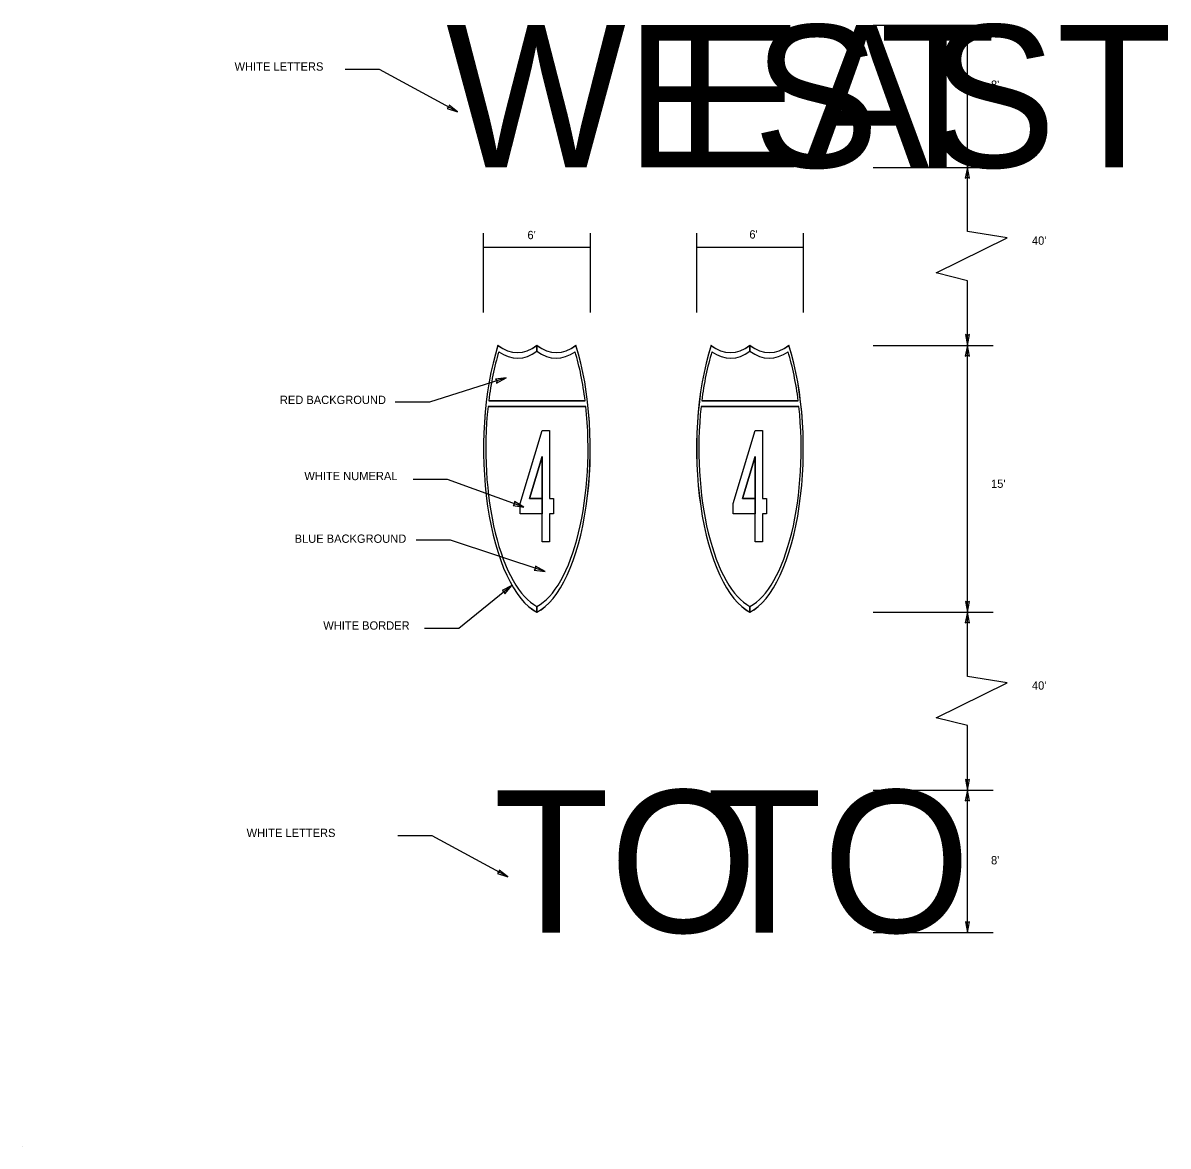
# Model space of a CAD drawing. Extents: x -274 to 353, y -329 to 85.
# Drawn here: x -273.7 to 112.5, y -328.7 to 50 of the extents above; entities that cross this region are included whole.
import ezdxf

# ---------------------------------------------------------------- set-up
doc = ezdxf.new("R2010")
doc.units = 0
for name, color, linetype in [('52', 7, 'Continuous'), ('AdhocPoint_dp', 7, 'Continuous'), ('DimLines_dp', 7, 'Continuous'), ('PavtMessage_Horizontal', 7, 'Continuous'), ('TextLabel', 7, 'Continuous')]:
    doc.layers.add(name, color=color, linetype=linetype)

msp = doc.modelspace()

# ---------------------------------------------------------------- linework, layer by layer
at = {"layer": '52'}
for p, q in [((44.85, 49.32), (44.15, 45.7)), ((45.52, 45.7), (44.85, 49.32)), ((44.15, 45.7), (44.85, 45.97)), ((44.85, 45.97), (45.52, 45.7)), ((-130.08, 21.6), (-130.64, 21.14)), ((-130.64, 21.14), (-127.13, 20)), ((-129.98, 22.34), (-130.08, 21.6)), ((-127.13, 20), (-129.98, 22.34)), ((44.85, 4.67), (44.17, 4.95)), ((44.17, 4.95), (44.85, 1.32)), ((44.85, 1.32), (45.55, 4.95)), ((45.55, 4.95), (44.85, 4.67)), ((44.85, 1.32), (44.15, -2.3)), ((45.52, -2.3), (44.85, 1.32)), ((44.15, -2.3), (44.85, -2.03)), ((44.85, -2.03), (45.52, -2.3)), ((44.85, -55.33), (44.17, -55.05)), ((44.17, -55.05), (44.85, -58.68)), ((44.85, -58.68), (45.55, -55.05)), ((45.55, -55.05), (44.85, -55.33)), ((44.85, -58.68), (44.15, -62.3)), ((45.52, -62.3), (44.85, -58.68)), ((44.15, -62.3), (44.85, -62.03)), ((44.85, -62.03), (45.52, -62.3)), ((-110.7, -69.68), (-114.37, -70.1)), ((-114.37, -70.1), (-113.9, -70.68)), ((-113.96, -71.41), (-110.7, -69.68)), ((-113.9, -70.68), (-113.96, -71.41)), ((-104.73, -113.23), (-107.9, -111.34)), ((-107.9, -111.34), (-107.88, -112.09)), ((-107.88, -112.09), (-108.36, -112.63)), ((-108.36, -112.63), (-104.73, -113.23)), ((-100.79, -133.89), (-101.26, -134.44)), ((-101.26, -134.44), (-97.61, -134.94)), ((-97.61, -134.94), (-100.83, -133.14)), ((-100.83, -133.14), (-100.79, -133.89)), ((-108.76, -139.62), (-112.01, -141.37)), ((-112.01, -141.37), (-111.35, -141.73)), ((-111.35, -141.73), (-111.14, -142.43)), ((-111.14, -142.43), (-108.76, -139.62)), ((44.85, -145.33), (44.17, -145.05)), ((44.17, -145.05), (44.85, -148.68)), ((44.85, -148.68), (45.55, -145.05)), ((45.55, -145.05), (44.85, -145.33)), ((44.85, -148.68), (44.15, -152.3)), ((45.52, -152.3), (44.85, -148.68)), ((44.15, -152.3), (44.85, -152.03)), ((44.85, -152.03), (45.52, -152.3)), ((44.85, -205.33), (44.17, -205.05)), ((44.17, -205.05), (44.85, -208.68)), ((44.85, -208.68), (45.55, -205.05)), ((45.55, -205.05), (44.85, -205.33)), ((44.85, -208.68), (44.15, -212.3)), ((44.15, -212.3), (44.85, -212.03)), ((45.52, -212.3), (44.85, -208.68)), ((44.85, -212.03), (45.52, -212.3)), ((-113.03, -235.61), (-113.12, -236.35)), ((-110.18, -237.95), (-113.03, -235.61)), ((-113.12, -236.35), (-113.69, -236.82)), ((-113.69, -236.82), (-110.18, -237.95)), ((44.85, -253.33), (44.17, -253.05)), ((44.17, -253.05), (44.85, -256.68)), ((44.85, -256.68), (45.55, -253.05)), ((45.55, -253.05), (44.85, -253.33))]:
    msp.add_line(p, q, dxfattribs=at)
at = {"layer": 'AdhocPoint_dp'}
msp.add_line((-273.71, -328.68), (-273.71, -328.68), dxfattribs=at)
at = {"layer": 'DimLines_dp'}
for p, q in [((13.04, 49.32), (48.19, 49.32)), ((44.85, 1.32), (44.85, 49.32)), ((-153.47, 34.31), (-165.05, 34.31)), ((-127.13, 20), (-153.47, 34.31)), ((13.04, 1.32), (48.19, 1.32)), ((44.85, -20.35), (44.85, 1.32)), ((-118.31, -47.57), (-118.31, -20.9)), ((-82.31, -47.57), (-82.31, -20.9)), ((-46.46, -47.57), (-46.46, -20.9)), ((-10.46, -47.57), (-10.46, -20.9)), ((34.33, -34.26), (58.21, -22.48)), ((58.21, -22.48), (44.85, -20.35)), ((-82.31, -25.74), (-118.31, -25.74)), ((-10.46, -25.74), (-46.46, -25.74)), ((44.85, -36.89), (34.33, -34.26)), ((44.85, -58.68), (44.85, -36.89)), ((13.04, -58.68), (53.52, -58.68)), ((44.85, -148.68), (44.85, -58.68)), ((-110.7, -69.68), (-136.57, -77.79)), ((-136.57, -77.79), (-148.15, -77.79)), ((-130.5, -103.91), (-142.07, -103.91)), ((-104.73, -113.23), (-130.5, -103.91)), ((-129.5, -124.41), (-141.07, -124.41)), ((-97.61, -134.94), (-129.5, -124.41)), ((-108.76, -139.62), (-126.67, -154.2)), ((13.04, -148.68), (53.52, -148.68)), ((44.85, -170.35), (44.85, -148.68)), ((-126.67, -154.2), (-138.24, -154.2)), ((34.33, -184.26), (58.21, -172.48)), ((58.21, -172.48), (44.85, -170.35)), ((44.85, -186.89), (34.33, -184.26)), ((44.85, -208.68), (44.85, -186.89)), ((13.04, -208.68), (53.52, -208.68)), ((44.85, -256.68), (44.85, -208.68)), ((-135.72, -224.08), (-147.29, -224.08)), ((-110.18, -237.95), (-135.72, -224.08)), ((13.04, -256.68), (53.52, -256.68))]:
    msp.add_line(p, q, dxfattribs=at)
at = {"layer": 'PavtMessage_Horizontal'}
for points in [[(-100.34, -58.68), (-100.34, -60.64)], [(-100.34, -60.64), (-100.34, -58.68)], [(-28.48, -58.68), (-28.48, -60.64)], [(-28.48, -60.64), (-28.48, -58.68)], [(-83.85, -79.3), (-116.83, -79.3)], [(-116.83, -79.3), (-83.85, -79.3)], [(-116.61, -77.43), (-84.07, -77.43)], [(-84.07, -77.43), (-116.61, -77.43)], [(-11.99, -79.3), (-44.97, -79.3)], [(-44.97, -79.3), (-11.99, -79.3)], [(-44.75, -77.43), (-12.21, -77.43)], [(-12.21, -77.43), (-44.75, -77.43)], [(-100.34, -148.68), (-100.34, -146.76)], [(-100.34, -146.76), (-100.34, -148.68)], [(-28.48, -148.68), (-28.48, -146.76)], [(-28.48, -146.76), (-28.48, -148.68)], [(-100.34, -148.66), (-100.34, -148.68)], [(-100.34, -148.68), (-100.34, -148.66)], [(-28.48, -148.66), (-28.48, -148.68)], [(-28.48, -148.68), (-28.48, -148.66)]]:
    msp.add_lwpolyline(points, dxfattribs=at)
for points in [[(-98.54, -124.93), (-98.54, -115.55), (-105.96, -115.55), (-105.96, -111.99), (-98.54, -87.43), (-96.14, -87.43), (-96.14, -110.3), (-94.71, -110.3), (-94.71, -115.55), (-96.14, -115.55), (-96.14, -124.93)], [(-94.71, -110.3), (-94.71, -115.55), (-96.14, -115.55), (-96.14, -124.93), (-98.54, -124.93), (-98.54, -96.14), (-102.82, -110.3), (-98.54, -110.3), (-98.54, -115.55), (-105.96, -115.55), (-105.96, -111.99), (-98.54, -87.43), (-96.14, -87.43), (-96.14, -110.3)], [(-94.71, -110.3), (-94.71, -115.55), (-96.14, -115.55), (-96.14, -124.93), (-98.54, -124.93), (-98.54, -96.14), (-102.82, -110.3), (-98.54, -110.3), (-98.54, -115.55), (-105.96, -115.55), (-105.96, -111.99), (-98.54, -87.43), (-96.14, -87.43), (-96.14, -110.3)], [(-26.68, -124.93), (-26.68, -115.55), (-34.11, -115.55), (-34.11, -111.99), (-26.68, -87.43), (-24.28, -87.43), (-24.28, -110.3), (-22.86, -110.3), (-22.86, -115.55), (-24.28, -115.55), (-24.28, -124.93)], [(-22.86, -110.3), (-22.86, -115.55), (-24.28, -115.55), (-24.28, -124.93), (-26.68, -124.93), (-26.68, -96.14), (-30.96, -110.3), (-26.68, -110.3), (-26.68, -115.55), (-34.11, -115.55), (-34.11, -111.99), (-26.68, -87.43), (-24.28, -87.43), (-24.28, -110.3)], [(-22.86, -110.3), (-22.86, -115.55), (-24.28, -115.55), (-24.28, -124.93), (-26.68, -124.93), (-26.68, -96.14), (-30.96, -110.3), (-26.68, -110.3), (-26.68, -115.55), (-34.11, -115.55), (-34.11, -111.99), (-26.68, -87.43), (-24.28, -87.43), (-24.28, -110.3)], [(-102.82, -110.3), (-98.54, -96.14), (-98.54, -110.3)], [(-30.96, -110.3), (-26.68, -96.14), (-26.68, -110.3)]]:
    msp.add_lwpolyline(points, close=True, dxfattribs=at)
for centre, major_axis, start_param, end_param in [((-95.84, -93.56), (0, 56.25), 0.901792, 2.940235), ((-95.84, -93.56), (0, 56.25), 0.901792, 2.940235), ((-95.84, -93.56), (0, 56.25), 0.901792, 2.940235), ((-95.84, -93.56), (0, 56.23), 0.902032, 2.940164), ((-95.84, -93.56), (0, 54.38), 0.92495, 1.269494), ((-95.84, -93.56), (0, 54.38), 0.92495, 1.269494), ((-106.91, -4.88), (0, 56.25), 2.845045, 3.43814), ((-106.91, -4.88), (0, 56.25), 2.845045, 3.43814), ((-106.91, -4.88), (0, 56.25), 2.845045, 3.43814), ((-106.91, -4.88), (0, 56.27), 2.845285, 3.438033), ((-106.91, -4.88), (0, 58.13), 2.867444, 3.428298), ((-106.91, -4.88), (0, 58.13), 2.867444, 3.428298), ((-93.76, -4.88), (0, 56.25), 2.845045, 3.43814), ((-104.84, -93.56), (0, 56.25), 3.34295, 5.381393), ((-104.84, -93.56), (0, 56.25), 3.342968, 5.381393), ((-93.76, -4.88), (0, 56.25), 2.845064, 3.43814), ((-93.76, -4.88), (0, 56.25), 2.845045, 3.43814), ((-104.84, -93.56), (0, 56.25), 3.342968, 5.381393), ((-104.84, -93.56), (0, 56.23), 3.34304, 5.381154), ((-93.76, -4.88), (0, 56.27), 2.845153, 3.4379), ((-93.76, -4.88), (0, 58.13), 2.854887, 3.415741), ((-93.76, -4.88), (0, 58.13), 2.854905, 3.415741), ((-104.84, -93.56), (0, 54.38), 5.013691, 5.358235), ((-104.84, -93.56), (0, 54.38), 5.013691, 5.358235), ((-23.98, -93.56), (0, 56.25), 0.901792, 2.940235), ((-23.98, -93.56), (0, 56.25), 0.901792, 2.940235), ((-23.98, -93.56), (0, 56.25), 0.901792, 2.940235), ((-23.98, -93.56), (0, 56.23), 0.902032, 2.940164), ((-23.98, -93.56), (0, 54.38), 0.92495, 1.269494), ((-23.98, -93.56), (0, 54.38), 0.92495, 1.269494), ((-35.06, -4.88), (0, 56.25), 2.845045, 3.43814), ((-35.06, -4.88), (0, 56.25), 2.845045, 3.43814), ((-35.06, -4.88), (0, 56.25), 2.845045, 3.43814), ((-35.06, -4.88), (0, 56.27), 2.845285, 3.438033), ((-35.06, -4.88), (0, 58.13), 2.867444, 3.428298), ((-35.06, -4.88), (0, 58.13), 2.867444, 3.428298), ((-21.91, -4.88), (0, 56.25), 2.845045, 3.43814), ((-32.98, -93.56), (0, 56.25), 3.34295, 5.381393), ((-32.98, -93.56), (0, 56.25), 3.342968, 5.381393), ((-21.91, -4.88), (0, 56.25), 2.845064, 3.43814), ((-21.91, -4.88), (0, 56.25), 2.845045, 3.43814), ((-32.98, -93.56), (0, 56.25), 3.342968, 5.381393), ((-32.98, -93.56), (0, 56.23), 3.34304, 5.381154), ((-21.91, -4.88), (0, 56.27), 2.845153, 3.4379), ((-21.91, -4.88), (0, 58.13), 2.854887, 3.415741), ((-21.91, -4.88), (0, 58.13), 2.854905, 3.415741), ((-32.98, -93.56), (0, 54.38), 5.013691, 5.358235), ((-32.98, -93.56), (0, 54.38), 5.013691, 5.358235), ((-95.84, -93.56), (0, 54.38), 1.30541, 2.933192), ((-95.84, -93.56), (0, 54.38), 1.30541, 2.933192), ((-104.84, -93.56), (0, 54.38), 3.349994, 4.977774), ((-104.84, -93.56), (0, 54.38), 3.350013, 4.977774), ((-23.98, -93.56), (0, 54.38), 1.30541, 2.933192), ((-23.98, -93.56), (0, 54.38), 1.30541, 2.933192), ((-32.98, -93.56), (0, 54.38), 3.349994, 4.977774), ((-32.98, -93.56), (0, 54.38), 3.350013, 4.977774)]:
    msp.add_ellipse(centre, major_axis=major_axis, ratio=0.399999, start_param=start_param, end_param=end_param, dxfattribs=at)

# ---------------------------------------------------------------- texts
for s, p in [('WEST', (-130.97, 1.32)), ('EAST', (-53.63, 1.32)), ('TO', (-115.08, -256.68)), ('TO', (-43.23, -256.68))]:
    msp.add_text(s, height=48, rotation=359.9999, dxfattribs=at).set_placement(p)
at = {"layer": 'TextLabel'}
for s, p in [('WHITE LETTERS', (-202.32, 33.94)), ("8'", (52.82, 27.81)), ("6'", (-103.53, -22.89)), ("6'", (-28.69, -22.68)), ("40'", (66.61, -24.77)), ('RED BACKGROUND', (-187.04, -78.47)), ('WHITE NUMERAL', (-178.78, -104.14)), ("15'", (52.82, -106.74)), ('BLUE BACKGROUND', (-182.06, -125.27)), ('WHITE BORDER', (-172.4, -154.55)), ("40'", (66.61, -174.77)), ('WHITE LETTERS', (-198.26, -224.47)), ("8'", (52.82, -233.7))]:
    msp.add_text(s, height=2.8, dxfattribs=at).set_placement(p)

doc.saveas('drawing.dxf')
